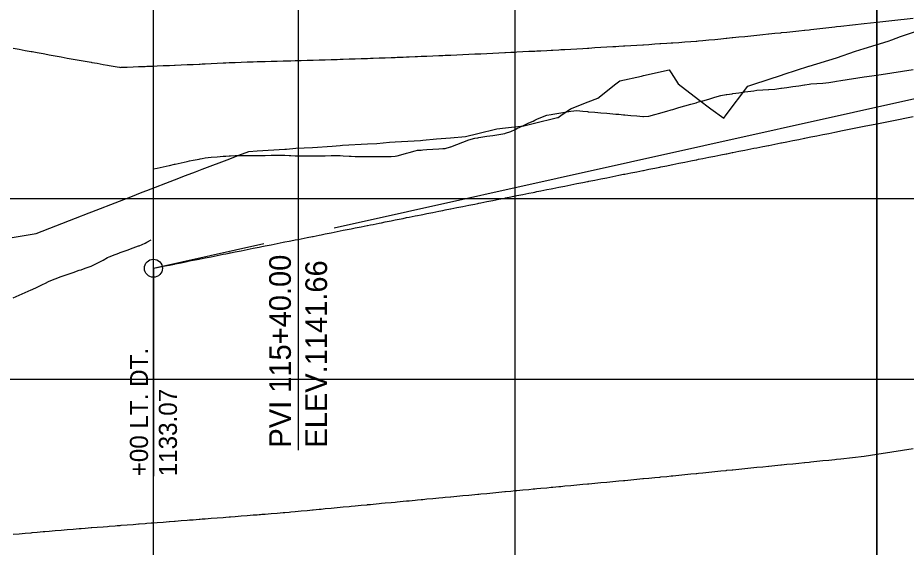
# Model space of a CAD drawing. Extents: x 688474 to 694748, y 765018 to 767373.
# Drawn here: x 692416.1 to 692661.7, y 765913.5 to 766059.8 of the extents above; entities that cross this region are included whole.
import ezdxf

# ---------------------------------------------------------------- set-up
doc = ezdxf.new("R2010")
doc.units = 0
for name, color, linetype in [('37', 7, 'Continuous'), ('R_Exist Surface', 7, 'Continuous'), ('R_No Plot', 7, 'Continuous'), ('R_Profile Work Left', 7, 'Continuous'), ('R_Profile Work Right', 7, 'Continuous'), ('R_Vert Alg', 7, 'Continuous'), ('R_Vert Alg Annot', 7, 'Continuous')]:
    doc.layers.add(name, color=color, linetype=linetype)

msp = doc.modelspace()

# ---------------------------------------------------------------- linework, layer by layer
at = {"layer": '37'}
for p, q in [((692453.59, 765809.92), (692453.59, 766359.92)), ((692553.59, 765809.92), (692553.59, 766359.92)), ((692653.59, 765809.92), (692653.59, 766359.92)), ((690853.59, 766009.92), (693453.59, 766009.92)), ((690853.59, 765959.92), (693453.59, 765959.92))]:
    msp.add_line(p, q, dxfattribs=at)
at = {"layer": 'R_Exist Surface'}
msp.add_lwpolyline([(692414.55, 765999.07), (692421.2, 766000.18), (692432.06, 766004.44), (692435.84, 766005.89), (692436.54, 766006.17), (692444.17, 766009.15), (692447.35, 766010.39), (692450.52, 766011.6), (692451.79, 766012.1), (692459.42, 766015.05), (692462.43, 766016.21), (692465.25, 766017.27), (692467.05, 766017.96), (692474.67, 766020.88), (692477.22, 766021.85), (692480, 766022.88), (692482.3, 766023.03), (692489.93, 766023.49), (692490.35, 766023.51), (692492.94, 766023.75), (692497.55, 766024.02), (692502.99, 766024.33), (692505.18, 766024.53), (692505.89, 766024.6), (692512.81, 766024.98), (692515.36, 766025.12), (692518.87, 766025.46), (692520.43, 766025.54), (692527.41, 766025.92), (692528.06, 766025.99), (692531.89, 766026.37), (692535.68, 766026.68), (692539.87, 766027.01), (692543.31, 766027.85), (692548.56, 766029.14), (692550.94, 766029.41), (692555.96, 766030), (692558.56, 766030.63), (692565.3, 766032.27), (692565.36, 766032.25), (692565.39, 766032.27), (692565.41, 766032.28), (692565.44, 766032.29), (692566.19, 766032.8), (692568.89, 766034.62), (692573.82, 766036.56), (692576.41, 766037.59), (692581.44, 766041.54), (692582.54, 766042.4), (692588.53, 766043.73), (692589.07, 766043.85), (692596.18, 766045.44), (692596.7, 766044.62), (692598.62, 766041.59), (692604.32, 766037.2), (692607.73, 766034.65), (692611.25, 766032.05), (692611.95, 766032.97), (692617.91, 766040.93), (692619.58, 766041.45), (692627.2, 766043.97), (692627.96, 766044.24), (692634.78, 766046.47), (692634.83, 766046.49), (692642.42, 766048.72), (692642.46, 766048.73), (692647.7, 766050.59), (692650.08, 766051.31), (692656.68, 766053.4), (692657.71, 766053.77), (692660.09, 766054.67), (692665.34, 766056.37)], dxfattribs=at)
at = {"layer": 'R_No Plot'}
msp.add_line((692653.59, 766099.88), (692653.59, 765796.18), dxfattribs=at)
at = {"layer": 'R_Profile Work Left'}
for points in [[(692453.59, 766018.09), (692454.64, 766018.31), (692456.3, 766018.66), (692457.95, 766019), (692458, 766019.01), (692459.42, 766019.33), (692459.61, 766019.37), (692461.27, 766019.76), (692462.93, 766020.12), (692463.59, 766020.25), (692464.58, 766020.45), (692466.24, 766020.77), (692466.54, 766020.82), (692467.05, 766020.92), (692467.9, 766021.09), (692469.55, 766021.3), (692471.21, 766021.42), (692472.87, 766021.54), (692473.59, 766021.59), (692474.53, 766021.66), (692474.67, 766021.67), (692474.88, 766021.68), (692476.18, 766021.74), (692477.84, 766021.75), (692479.5, 766021.76), (692481.16, 766021.78), (692482.3, 766021.79), (692482.81, 766021.79), (692483.23, 766021.8), (692483.59, 766021.8), (692484.47, 766021.81), (692486.13, 766021.82), (692487.79, 766021.84), (692489.44, 766021.83), (692489.93, 766021.82), (692491.1, 766021.77), (692491.57, 766021.74), (692492.76, 766021.68), (692493.59, 766021.68), (692494.42, 766021.69), (692496.07, 766021.69), (692497.55, 766021.7), (692497.73, 766021.7), (692499.39, 766021.71), (692499.92, 766021.71), (692501.05, 766021.72), (692502.7, 766021.73), (692503.59, 766021.73), (692504.36, 766021.74), (692505.18, 766021.74), (692506.02, 766021.68), (692507.68, 766021.58), (692508.26, 766021.55), (692509.33, 766021.48), (692510.99, 766021.47), (692512.65, 766021.47), (692512.81, 766021.47), (692513.59, 766021.47), (692514.31, 766021.47), (692515.96, 766021.47), (692516.61, 766021.48), (692517.62, 766021.48), (692519.28, 766021.49), (692520.43, 766021.54), (692520.94, 766021.68), (692522.59, 766022.15), (692523.59, 766022.44), (692524.25, 766022.62), (692525.91, 766023.1), (692526.61, 766023.2), (692527.57, 766023.27), (692528.06, 766023.3), (692529.22, 766023.38), (692530.88, 766023.49), (692532.54, 766023.61), (692533.59, 766023.68), (692534.2, 766023.72), (692535.68, 766024.12), (692535.85, 766024.18), (692537.51, 766024.81), (692539.17, 766025.44), (692540.83, 766026.07), (692542.48, 766026.54), (692543.31, 766026.67), (692543.59, 766026.71), (692544.14, 766026.8), (692545.8, 766027.07), (692547.46, 766027.33), (692549.11, 766027.6), (692550.77, 766027.87), (692550.94, 766027.9), (692552.43, 766028.4), (692553.59, 766028.95), (692554.09, 766029.19), (692555.74, 766029.97), (692557.4, 766030.75), (692558.56, 766031.3), (692559.06, 766031.54), (692559.61, 766031.8), (692560.72, 766032.29), (692562.37, 766032.9), (692563.59, 766033.11), (692564.03, 766033.19), (692565.69, 766033.48), (692566.19, 766033.56), (692567.35, 766033.76), (692569, 766034.05), (692570.66, 766034.16), (692572.32, 766034.02), (692573.59, 766033.9), (692573.82, 766033.88), (692573.97, 766033.87), (692575.63, 766033.73), (692577.29, 766033.58), (692578.95, 766033.44), (692580.6, 766033.29), (692581.44, 766033.22), (692582.26, 766033.15), (692583.59, 766033.03), (692583.92, 766033), (692585.58, 766032.86), (692587.23, 766032.71), (692588.89, 766032.57), (692589.07, 766032.56), (692590.55, 766032.6), (692592.21, 766033.09), (692593.59, 766033.49), (692593.86, 766033.57), (692595.52, 766034.04), (692596.7, 766034.38), (692597.18, 766034.51), (692598.84, 766034.99), (692600.49, 766035.46), (692602.15, 766035.94), (692603.59, 766036.35), (692603.81, 766036.41), (692604.32, 766036.56), (692605.47, 766036.89), (692607.12, 766037.37), (692608.78, 766037.85), (692610.44, 766038.33), (692611.95, 766038.62), (692612.1, 766038.64), (692613.59, 766038.84), (692613.75, 766038.87), (692615.41, 766039.1), (692617.07, 766039.32), (692618.73, 766039.55), (692619.58, 766039.67), (692620.38, 766039.78), (692622.04, 766039.9), (692623.59, 766039.99), (692623.7, 766039.99), (692625.36, 766040.09), (692627.01, 766040.33), (692627.2, 766040.36), (692628.67, 766040.57), (692630.33, 766040.81), (692631.99, 766041.05), (692633.59, 766041.28), (692633.64, 766041.29), (692634.83, 766041.46), (692635.3, 766041.53), (692636.96, 766041.64), (692638.62, 766041.74), (692640.27, 766041.97), (692641.93, 766042.22), (692642.46, 766042.3), (692643.59, 766042.47), (692650.08, 766043.47), (692653.59, 766044), (692657.71, 766044.64), (692663.59, 766045.55)], [(692453.59, 765990.62), (692454.64, 765990.83), (692456.3, 765991.16), (692457.95, 765991.49), (692458, 765991.5), (692459.42, 765991.78), (692459.61, 765991.82), (692461.27, 765992.15), (692462.93, 765992.48), (692463.59, 765992.62), (692464.58, 765992.81), (692466.24, 765993.15), (692466.54, 765993.21), (692467.05, 765993.31), (692467.9, 765993.48), (692469.55, 765993.81), (692471.21, 765994.14), (692472.87, 765994.47), (692473.59, 765994.61), (692474.53, 765994.8), (692474.67, 765994.83), (692474.88, 765994.87), (692476.18, 765995.13), (692477.84, 765995.46), (692479.5, 765995.79), (692481.16, 765996.12), (692482.3, 765996.35), (692482.81, 765996.45), (692483.23, 765996.54), (692483.59, 765996.61), (692484.47, 765996.78), (692486.13, 765997.12), (692487.79, 765997.45), (692489.44, 765997.78), (692489.93, 765997.87), (692491.1, 765998.11), (692491.57, 765998.2), (692492.76, 765998.44), (692493.59, 765998.6), (692494.42, 765998.77), (692496.07, 765999.1), (692497.55, 765999.4), (692497.73, 765999.43), (692499.39, 765999.76), (692499.92, 765999.87), (692501.05, 766000.09), (692502.7, 766000.42), (692503.59, 766000.6), (692504.36, 766000.75), (692505.18, 766000.92), (692506.02, 766001.09), (692507.68, 766001.42), (692508.26, 766001.53), (692509.33, 766001.75), (692510.99, 766002.08), (692512.65, 766002.41), (692512.81, 766002.44), (692513.59, 766002.6), (692514.31, 766002.74), (692515.96, 766003.07), (692516.61, 766003.2), (692517.62, 766003.4), (692519.28, 766003.73), (692520.43, 766003.96), (692520.94, 766004.06), (692522.59, 766004.39), (692523.59, 766004.59), (692524.25, 766004.72), (692525.91, 766005.06), (692526.61, 766005.19), (692527.57, 766005.39), (692528.06, 766005.48), (692529.22, 766005.72), (692530.88, 766006.05), (692532.54, 766006.38), (692533.59, 766006.59), (692534.2, 766006.71), (692535.68, 766007.01), (692535.85, 766007.04), (692537.51, 766007.37), (692539.17, 766007.7), (692540.83, 766008.03), (692542.48, 766008.36), (692543.31, 766008.53), (692543.59, 766008.58), (692544.14, 766008.69), (692545.8, 766009.03), (692547.46, 766009.36), (692549.11, 766009.69), (692550.77, 766010.02), (692550.94, 766010.05), (692552.43, 766010.35), (692553.59, 766010.58), (692554.09, 766010.68), (692555.74, 766011.01), (692557.4, 766011.34), (692558.56, 766011.57), (692559.06, 766011.67), (692559.61, 766011.78), (692560.72, 766012), (692562.37, 766012.33), (692563.59, 766012.58), (692564.03, 766012.66), (692565.69, 766013), (692566.19, 766013.1), (692567.35, 766013.33), (692569, 766013.66), (692570.66, 766013.99), (692572.32, 766014.32), (692573.59, 766014.57), (692573.82, 766014.62), (692573.97, 766014.65), (692575.63, 766014.98), (692577.29, 766015.31), (692578.95, 766015.64), (692580.6, 766015.97), (692581.44, 766016.14), (692582.26, 766016.3), (692583.59, 766016.57), (692583.92, 766016.63), (692585.58, 766016.97), (692587.23, 766017.3), (692588.89, 766017.63), (692589.07, 766017.66), (692590.55, 766017.96), (692592.21, 766018.29), (692593.59, 766018.56), (692593.86, 766018.62), (692595.52, 766018.95), (692596.7, 766019.18), (692597.18, 766019.28), (692598.84, 766019.61), (692600.49, 766019.94), (692602.15, 766020.27), (692603.59, 766020.56), (692603.81, 766020.6), (692604.32, 766020.71), (692605.47, 766020.94), (692607.12, 766021.27), (692608.78, 766021.6), (692610.44, 766021.93), (692611.95, 766022.23), (692612.1, 766022.26), (692613.59, 766022.56), (692613.75, 766022.59), (692615.41, 766022.92), (692617.07, 766023.25), (692618.73, 766023.58), (692619.58, 766023.75), (692620.38, 766023.91), (692622.04, 766024.24), (692623.59, 766024.55), (692623.7, 766024.57), (692625.36, 766024.9), (692627.01, 766025.24), (692627.2, 766025.27), (692628.67, 766025.57), (692630.33, 766025.9), (692631.99, 766026.23), (692633.59, 766026.55), (692633.64, 766026.56), (692634.83, 766026.8), (692635.3, 766026.89), (692636.96, 766027.22), (692638.62, 766027.55), (692640.27, 766027.88), (692641.93, 766028.21), (692642.46, 766028.32), (692643.59, 766028.54), (692650.08, 766029.84), (692653.59, 766030.54), (692657.71, 766031.36), (692663.59, 766032.54)], [(692414.86, 765982.4), (692416.52, 765983.15), (692418.17, 765983.89), (692419.83, 765984.64), (692420.09, 765984.75), (692421.49, 765985.41), (692423.15, 765986.21), (692423.59, 765986.43), (692424.8, 765987.04), (692426.46, 765987.73), (692428.12, 765988.31), (692429.78, 765988.88), (692431.43, 765989.46), (692433.09, 765990.04), (692433.59, 765990.21), (692434.75, 765990.62), (692436.41, 765991.2), (692436.54, 765991.24), (692438.06, 765991.98), (692439.72, 765992.89), (692440.92, 765993.54), (692441.38, 765993.8), (692443.04, 765994.42), (692443.59, 765994.63), (692444.17, 765994.84), (692444.38, 765994.92), (692444.69, 765995.03), (692446.35, 765995.64), (692448.01, 765996.25), (692449.46, 765996.78), (692449.67, 765996.85), (692451.32, 765997.53), (692451.79, 765997.8), (692452.98, 765998.46)]]:
    msp.add_lwpolyline(points, dxfattribs=at)
at = {"layer": 'R_Profile Work Right'}
for points in [[(692414.86, 766051.43), (692416.52, 766051.12), (692418.17, 766050.82), (692419.83, 766050.51), (692420.09, 766050.47), (692421.49, 766050.21), (692423.15, 766049.91), (692423.59, 766049.83), (692424.8, 766049.61), (692426.46, 766049.31), (692428.12, 766049.01), (692429.78, 766048.71), (692431.43, 766048.42), (692433.09, 766048.12), (692433.59, 766048.03), (692434.75, 766047.83), (692436.41, 766047.53), (692436.54, 766047.51), (692438.06, 766047.24), (692439.72, 766046.95), (692440.92, 766046.75), (692441.38, 766046.66), (692443.04, 766046.37), (692443.59, 766046.27), (692444.17, 766046.17), (692444.38, 766046.13), (692444.69, 766046.14), (692446.35, 766046.21), (692448.01, 766046.27), (692449.46, 766046.33), (692449.67, 766046.34), (692451.32, 766046.4), (692451.79, 766046.42), (692452.98, 766046.47), (692453.59, 766046.49), (692454.64, 766046.54), (692456.3, 766046.6), (692457.95, 766046.67), (692458, 766046.68), (692459.42, 766046.74), (692459.61, 766046.75), (692461.27, 766046.82), (692462.93, 766046.89), (692463.59, 766046.92), (692464.58, 766046.96), (692466.24, 766047.04), (692466.54, 766047.05), (692467.05, 766047.08), (692467.9, 766047.11), (692469.55, 766047.19), (692471.21, 766047.27), (692472.87, 766047.35), (692473.59, 766047.38), (692474.53, 766047.43), (692474.67, 766047.44), (692474.88, 766047.45), (692476.18, 766047.51), (692477.84, 766047.59), (692479.5, 766047.64), (692481.16, 766047.68), (692482.3, 766047.71), (692482.81, 766047.72), (692483.23, 766047.73), (692483.59, 766047.74), (692484.47, 766047.76), (692486.13, 766047.8), (692487.79, 766047.85), (692489.44, 766047.89), (692489.93, 766047.9), (692491.1, 766047.93), (692491.57, 766047.95), (692492.76, 766047.98), (692493.59, 766048), (692494.42, 766048.03), (692496.07, 766048.07), (692497.55, 766048.12), (692497.73, 766048.12), (692499.39, 766048.17), (692499.92, 766048.19), (692501.05, 766048.22), (692502.7, 766048.28), (692503.59, 766048.3), (692504.36, 766048.33), (692505.18, 766048.36), (692506.02, 766048.38), (692507.68, 766048.44), (692508.26, 766048.46), (692509.33, 766048.49), (692510.99, 766048.55), (692512.65, 766048.61), (692512.81, 766048.61), (692513.59, 766048.64), (692514.31, 766048.67), (692515.96, 766048.73), (692516.61, 766048.75), (692517.62, 766048.79), (692519.28, 766048.85), (692520.43, 766048.89), (692520.94, 766048.91), (692522.59, 766048.98), (692523.59, 766049.02), (692524.25, 766049.04), (692525.91, 766049.11), (692526.61, 766049.14), (692527.57, 766049.18), (692528.06, 766049.2), (692529.22, 766049.24), (692530.88, 766049.31), (692532.54, 766049.38), (692533.59, 766049.43), (692534.2, 766049.45), (692535.68, 766049.52), (692535.85, 766049.53), (692537.51, 766049.6), (692539.17, 766049.67), (692540.83, 766049.75), (692542.48, 766049.83), (692543.31, 766049.86), (692543.59, 766049.88), (692544.14, 766049.9), (692545.8, 766049.98), (692547.46, 766050.06), (692549.11, 766050.14), (692550.77, 766050.22), (692550.94, 766050.23), (692552.43, 766050.3), (692553.59, 766050.36), (692554.09, 766050.39), (692555.74, 766050.47), (692557.4, 766050.56), (692558.56, 766050.62), (692559.06, 766050.64), (692559.61, 766050.67), (692560.72, 766050.73), (692562.37, 766050.82), (692563.59, 766050.89), (692564.03, 766050.91), (692565.69, 766051), (692566.19, 766051.03), (692567.35, 766051.09), (692569, 766051.18), (692570.66, 766051.28), (692572.32, 766051.37), (692573.59, 766051.45), (692573.82, 766051.46), (692573.97, 766051.47), (692575.63, 766051.57), (692577.29, 766051.66), (692578.95, 766051.76), (692580.6, 766051.86), (692581.44, 766051.91), (692582.26, 766051.96), (692583.59, 766052.04), (692583.92, 766052.06), (692585.58, 766052.17), (692587.23, 766052.27), (692588.89, 766052.38), (692589.07, 766052.39), (692590.55, 766052.48), (692592.21, 766052.59), (692593.59, 766052.68), (692593.86, 766052.7), (692595.52, 766052.8), (692596.7, 766052.88), (692597.18, 766052.91), (692598.84, 766053.03), (692600.49, 766053.14), (692602.15, 766053.25), (692603.59, 766053.35), (692603.81, 766053.37), (692604.32, 766053.42), (692605.47, 766053.53), (692607.12, 766053.69), (692608.78, 766053.86), (692610.44, 766054.02), (692611.95, 766054.17), (692612.1, 766054.18), (692613.59, 766054.33), (692613.75, 766054.35), (692615.41, 766054.52), (692617.07, 766054.68), (692618.73, 766054.85), (692619.58, 766054.94), (692620.38, 766055.02), (692622.04, 766055.19), (692623.59, 766055.35), (692623.7, 766055.36), (692625.36, 766055.54), (692627.01, 766055.71), (692627.2, 766055.73), (692628.67, 766055.89), (692630.33, 766056.06), (692631.99, 766056.24), (692633.59, 766056.41), (692633.64, 766056.42), (692634.83, 766056.54), (692635.3, 766056.6), (692636.96, 766056.78), (692638.62, 766056.96), (692640.27, 766057.14), (692641.93, 766057.32), (692642.46, 766057.38), (692643.59, 766057.51), (692650.08, 766058.23), (692653.59, 766058.62), (692657.71, 766059.08), (692663.59, 766059.73)], [(692414.86, 765917.12), (692416.52, 765917.26), (692418.17, 765917.4), (692419.83, 765917.54), (692420.09, 765917.56), (692421.49, 765917.68), (692423.15, 765917.82), (692423.59, 765917.86), (692424.8, 765917.96), (692426.46, 765918.1), (692428.12, 765918.24), (692429.78, 765918.38), (692431.43, 765918.51), (692433.09, 765918.65), (692433.59, 765918.7), (692434.75, 765918.79), (692436.41, 765918.93), (692436.54, 765918.94), (692438.06, 765919.06), (692439.72, 765919.19), (692440.92, 765919.29), (692441.38, 765919.32), (692443.04, 765919.45), (692443.59, 765919.49), (692444.17, 765919.54), (692444.38, 765919.56), (692444.69, 765919.58), (692446.35, 765919.71), (692448.01, 765919.84), (692449.46, 765919.95), (692449.67, 765919.97), (692451.32, 765920.1), (692451.79, 765920.13), (692452.98, 765920.23), (692453.59, 765920.27), (692454.64, 765920.36), (692456.3, 765920.49), (692457.95, 765920.61), (692458, 765920.62), (692459.42, 765920.73), (692459.61, 765920.74), (692461.27, 765920.87), (692462.93, 765921), (692463.59, 765921.05), (692464.58, 765921.13), (692466.24, 765921.26), (692466.54, 765921.28), (692467.05, 765921.32), (692467.9, 765921.39), (692469.55, 765921.52), (692471.21, 765921.65), (692472.87, 765921.78), (692473.59, 765921.83), (692474.53, 765921.91), (692474.67, 765921.92), (692474.88, 765921.94), (692476.18, 765922.04), (692477.84, 765922.17), (692479.5, 765922.3), (692481.16, 765922.43), (692482.3, 765922.51), (692482.81, 765922.55), (692483.23, 765922.59), (692483.59, 765922.61), (692484.47, 765922.68), (692486.13, 765922.81), (692487.79, 765922.94), (692489.44, 765923.08), (692489.93, 765923.12), (692491.1, 765923.24), (692491.57, 765923.28), (692492.76, 765923.39), (692493.59, 765923.47), (692494.42, 765923.55), (692496.07, 765923.71), (692497.55, 765923.85), (692497.73, 765923.86), (692499.39, 765924.02), (692499.92, 765924.07), (692501.05, 765924.18), (692502.7, 765924.34), (692503.59, 765924.42), (692504.36, 765924.49), (692505.18, 765924.57), (692506.02, 765924.65), (692507.68, 765924.81), (692508.26, 765924.86), (692509.33, 765924.96), (692510.99, 765925.12), (692512.65, 765925.28), (692512.81, 765925.29), (692513.59, 765925.37), (692514.31, 765925.43), (692515.96, 765925.59), (692516.61, 765925.65), (692517.62, 765925.75), (692519.28, 765925.91), (692520.43, 765926.01), (692520.94, 765926.06), (692522.59, 765926.22), (692523.59, 765926.31), (692524.25, 765926.38), (692525.91, 765926.53), (692526.61, 765926.6), (692527.57, 765926.69), (692528.06, 765926.74), (692529.22, 765926.85), (692530.88, 765927), (692532.54, 765927.16), (692533.59, 765927.26), (692534.2, 765927.31), (692535.68, 765927.46), (692535.85, 765927.47), (692537.51, 765927.63), (692539.17, 765927.78), (692540.83, 765927.94), (692542.48, 765928.1), (692543.31, 765928.18), (692543.59, 765928.2), (692544.14, 765928.25), (692545.8, 765928.41), (692547.46, 765928.57), (692549.11, 765928.72), (692550.77, 765928.88), (692550.94, 765928.9), (692552.43, 765929.04), (692553.59, 765929.15), (692554.09, 765929.19), (692555.74, 765929.35), (692557.4, 765929.5), (692558.56, 765929.61), (692559.06, 765929.66), (692559.61, 765929.71), (692560.72, 765929.82), (692562.37, 765929.97), (692563.59, 765930.09), (692564.03, 765930.13), (692565.69, 765930.29), (692566.19, 765930.33), (692567.35, 765930.44), (692569, 765930.6), (692570.66, 765930.75), (692572.32, 765930.91), (692573.59, 765931.03), (692573.82, 765931.05), (692573.97, 765931.07), (692575.63, 765931.22), (692577.29, 765931.38), (692578.95, 765931.53), (692580.6, 765931.69), (692581.44, 765931.77), (692582.26, 765931.85), (692583.59, 765931.97), (692583.92, 765932), (692585.58, 765932.16), (692587.23, 765932.31), (692588.89, 765932.47), (692589.07, 765932.49), (692590.55, 765932.63), (692592.21, 765932.78), (692593.59, 765932.91), (692593.86, 765932.94), (692595.52, 765933.1), (692596.7, 765933.22), (692597.18, 765933.27), (692598.84, 765933.43), (692600.49, 765933.6), (692602.15, 765933.77), (692603.59, 765933.91), (692603.81, 765933.93), (692604.32, 765933.98), (692605.47, 765934.1), (692607.12, 765934.27), (692608.78, 765934.43), (692610.44, 765934.6), (692611.95, 765934.75), (692612.1, 765934.77), (692613.59, 765934.92), (692613.75, 765934.93), (692615.41, 765935.1), (692617.07, 765935.27), (692618.73, 765935.44), (692619.58, 765935.52), (692620.38, 765935.6), (692622.04, 765935.77), (692623.59, 765935.93), (692623.7, 765935.94), (692625.36, 765936.11), (692627.01, 765936.27), (692627.2, 765936.29), (692628.67, 765936.44), (692630.33, 765936.61), (692631.99, 765936.78), (692633.59, 765936.94), (692633.64, 765936.95), (692634.83, 765937.07), (692635.3, 765937.11), (692636.96, 765937.28), (692638.62, 765937.45), (692640.27, 765937.62), (692641.93, 765937.79), (692642.46, 765937.84), (692643.59, 765937.95), (692650.08, 765938.69), (692653.59, 765939.24), (692657.71, 765939.88), (692663.59, 765940.8)]]:
    msp.add_lwpolyline(points, dxfattribs=at)
at = {"layer": 'R_Vert Alg'}
for p, q in [((692503.54, 766001.76), (692951.23, 766101.59)), ((692453.59, 765990.62), (692484.07, 765997.42))]:
    msp.add_line(p, q, dxfattribs=at)
msp.add_circle((692453.59, 765990.62), 2.5, dxfattribs=at)
at = {"layer": 'R_Vert Alg Annot'}
for p, q in [((692493.59, 766076.52), (692493.59, 765940.34)), ((692453.59, 765990.62), (692453.59, 765933.12))]:
    msp.add_line(p, q, dxfattribs=at)

# ---------------------------------------------------------------- texts
for s, height, p in [('PVI 115+40.00', 6, (692491.59, 765941.05)), ('ELEV.1141.66', 6, (692501.59, 765941.05)), ('+00 LT. DT.', 5, (692452.09, 765933.12)), ('1133.07', 5, (692460.09, 765933.12))]:
    msp.add_text(s, height=height, rotation=90, dxfattribs=at).set_placement(p)

doc.saveas('drawing.dxf')
